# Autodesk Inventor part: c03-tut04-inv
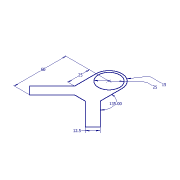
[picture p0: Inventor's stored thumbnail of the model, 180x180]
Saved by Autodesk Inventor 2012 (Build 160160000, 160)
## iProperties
Created: 2010-01
Part Number: c03-tut04-inv
Document SubType Name: Modeling
Designer: CADSoft
Density: 1 g/cm^3
Material: Default
Author: CADSoft
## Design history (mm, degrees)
sketch "Sketch1"
  geometry: L1 (-41.161, -51.161)-(-32.322, -60); L2 (-32.322, -60)-(-6.25, -33.928); L3 (-6.25, -33.928)-(6.25, -33.928); L4 (6.25, -33.928)-(32.322, -60); L5 (32.322, -60)-(41.161, -51.161); L6 (41.161, -51.161)-(15, -25); L7 (15, -25)-(15, 0); L8 (-15, 0)-(-15, -25); L9 (-15, -25)-(-41.161, -51.161); C1 r 12.5 at (0, 0); A1 r 15 centre (0, 0) between (15, 0) and (-15, 0); 2 further points
  constraints: 18 end point, 5 equal length, 3 coincident, 3 parallel, 2 centre point, 2 perpendicular, 2 point on circle, 2 tangent, 1 horizontal, 1 vertical, 1 other
  dimensions: "d0" = 25 distance of L8.start L8.end; "d1" = 60 vertical distance of L1.end A1.centre; "d2" = 12.5 distance of L4.end L5.end; "d3" = 135 deg angle of L6 L7; "d4" = 15 radius of A1; "d5" = 25 diameter of C1
